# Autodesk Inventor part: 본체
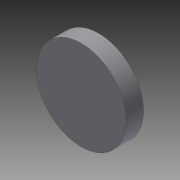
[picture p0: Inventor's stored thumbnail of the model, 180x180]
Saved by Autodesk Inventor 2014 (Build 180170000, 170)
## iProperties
Created: 2015-04
Part Number: 본체
Material: 일반
Document SubType Name: Modeling
Designer: basic
Density: 1 g/cm^3
Appearance: 기본값
Author: basic
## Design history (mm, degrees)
sketch "스케치1"
  geometry: C1 r 95 at (0, 0); 1 further point
  constraints: 1 centre point, 1 coincident
  dimensions: "d0" = 190 diameter of C1
extrude "돌출1" new body sketch "스케치1" distance "d1" = 37; taper "d2" = 0 deg
sketch "스케치2"
  geometry: L1 (47.117, 12)-(76.916, 12); L2 (-76.916, 12)-(-47.117, 12); C1 r 95 at (0, 0) reference; A1 r 90 centre (0, 0) between (86.53, 24.75) and (-86.53, 24.75); A2 r 42 centre (0, 0) between (38.056, 17.769) and (-38.056, 17.769); A3 r 10 centre (-47.117, 22) between (-47.117, 12) and (-38.056, 17.769); A4 r 10 centre (47.117, 22) between (38.056, 17.769) and (47.117, 12); A5 r 10 centre (-76.916, 22) between (-86.53, 24.75) and (-76.916, 12); A6 r 10 centre (76.916, 22) between (76.916, 12) and (86.53, 24.75)
  constraints: 12 point on circle, 12 tangent, 6 centre point, 4 end point, 3 equal radius, 2 coincident, 2 horizontal
  dimensions: "d3" = 180 diameter of A1; "d5" = 84 diameter of A2; "d6" = 20 diameter of A4; "d7" = 12 distance from line of C1.centre L2
extrude "돌출2" cut sketch "스케치2" distance "d8" = 25; taper "d9" = 0 deg
sketch "스케치4"
  geometry: L1 (76.916, 12)-(47.117, 12) reference; L2 (-47.117, 12)-(-76.916, 12) reference; C1 r 95 at (0, 0) reference; C2 r 90 at (0, 0); A1 r 10 centre (76.916, 22) between (76.916, 12) and (86.53, 24.75) reference; A2 r 10 centre (47.117, 22) between (38.056, 17.769) and (47.117, 12) reference; A3 r 42 centre (0, 0) between (38.056, 17.769) and (-38.056, 17.769) reference; A4 r 10 centre (-47.117, 22) between (-47.117, 12) and (-38.056, 17.769) reference; A5 r 10 centre (-76.916, 22) between (-86.53, 24.75) and (-76.916, 12) reference; A6 r 90 centre (0, 0) between (86.53, 24.75) and (-86.53, 24.75) reference
  constraints: 1 centre point, 1 coincident
  dimensions: "d22" = 180 diameter of C2
extrude "돌출3" cut sketch "스케치4" distance "d23" = 10; taper "d24" = 0 deg
node "솔리드1"
other parameters: "d4" = 12, "d14" = 82, "d16" = 118, "d26" = 118, "d28" = 5
